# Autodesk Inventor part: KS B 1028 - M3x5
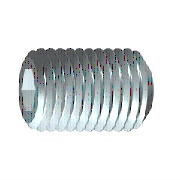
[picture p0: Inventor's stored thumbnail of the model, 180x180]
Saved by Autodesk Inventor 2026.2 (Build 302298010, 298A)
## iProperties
Created: 2025-01
Part Number: KS B 1028 - M3x5
Material: 강철, 연강
Description: 6각 소켓 머리 없는 멈춤 나사
Document SubType Name: Modeling
Standard: KS B 1028
Designer: work
Standards Organization: KS
Language: ko-KR
Size Designation: M3x5
Categories: <MemberInstance><Categories><Category DisplayName="조임쇠" InternalName="e4da775c-781d-43d5-af7c-5136215cf5a6" Mnemonic="FSTN"><Category DisplayName="볼트" InternalN
Density: 7.85 g/cm^3
Appearance: 반연마
IsCustomPart: 1
Author: work
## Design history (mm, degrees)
revolve "본체" stored, may be unused: angle "d6" = 90 deg
sketch "스케치2"
  geometry: L1 (0.866, 0)-(0.433, -0.75); L2 (0.433, -0.75)-(-0.433, -0.75); L3 (-0.433, -0.75)-(-0.866, 0); L4 (-0.866, 0)-(-0.433, 0.75); L5 (-0.433, 0.75)-(0.433, 0.75); L6 (0.433, 0.75)-(0.866, 0); C1 r 1.5 at (0, 0) reference; A1 r 0.866 centre (0, 0) between (0.866, 0) and (0.433, -0.75) reference; 1 further point
  constraints: 12 end point, 2 point on circle, 1 coincident, 1 horizontal, 11 other
extrude "슬롯" join sketch "스케치2" distance "d8" = 2 (= INTI); taper "d9" = 0 deg
workaxis "Work Axis1"
workplane "Work Plane1"
body "Solid1"
chamfer "모따기1" distance "d10" = 0.8 (= -0.5 x SPD + 0.5 x NND); stored, may be unused: angle "d11" = 45 deg (= FAWI), second distance "d33" = 0.8 (= -0.5 x SPD + 0.5 x NND)
feature "스레드" dims "d14" = 5 (= NLG), "d15" = 0
chamfer "모따기2" distance "d12" = 0.30673 (= -0.5 x GD1 + 0.5 x NND); stored, may be unused: angle "d13" = 45 deg (= FAWI), second distance "d34" = 0.30673 (= -0.5 x GD1 + 0.5 x NND)
sketch "스케치1"
  geometry: L1 (0.404, 0)-(2.5, 0); L2 (5, 0.866)-(5, 1.5); L3 (5, 1.5)-(0, 1.5); L4 (5, 0.866)-(3, 0.866); L5 (3, 0.866)-(2.5, 0); L6 (0, 0.7)-(0.404, 0); L7 (0, -0.3)-(0, 1.8) reference; L8 (0, 0.7)-(0, 1.5); 1 further point
  constraints: 14 end point, 2 parallel, 2 perpendicular, 2 point on line, 1 horizontal
  dimensions: "d0" = 2 distance of L2.start L4.end (= INTI); "d1" = 60 deg angle of L5 L1; "d2" = 3 diameter of L3 L1 (= NND); "d3" = 1.73205 diameter of L4 L1 (= 1.1547 x SW); "d4" = 5 distance from line of L2 L6.start (= NLG); "d5" = 60 deg angle of L1 L6 (= 0.5 x ANG); "d7" = 1.4 diameter of L6.start L1 (= SPD)
other parameters: "NND" = 3 [user parameter; used in 5 equation terms], "NLG" = 5 [user parameter; used in 2 equation terms], "INTI" = 2 [user parameter; used in 2 equation terms], "FAWI" = 45 deg [user parameter; used in 2 equation terms], "SW" = 1.5 [user parameter; used in 2 equation terms], "GD1" = 2.38655 (= THREADDIA - 1.2269 x PTC) [user parameter; used in 2 equation terms], "ANG" = 120 deg [user parameter; used in 1 equation term], "FAWI1" = 45 deg [user parameter], "SPD" = 1.4 [user parameter; used in 3 equation terms], "d16" = 0, "d35" = 0, "d37" = 0, "GUL" = 0.30673 (= 0.61345 x PTC) [user parameter], "TOA" = 30 deg [user parameter], "THREADDIA" = 3 [user parameter; used in 1 equation term], "PTC" = 0.5 [user parameter; used in 4 equation terms], "GAL" = 0.30673 (= 0.61345 x PTC) [user parameter], "E0" = 1.7325 (= 1.155 x SW) [user parameter]
